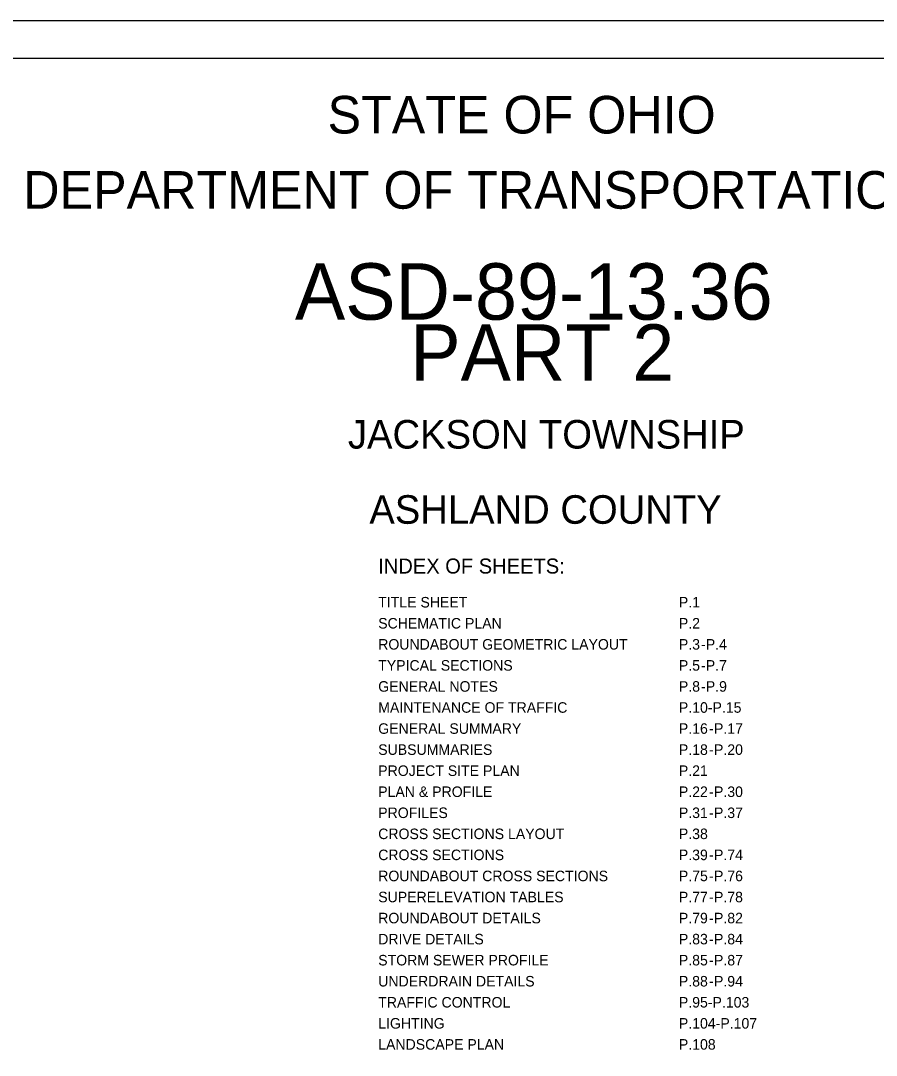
# Model space of a CAD drawing. Extents: x 0 to 72, y -85 to 22.
# Drawn here: x 9.89 to 21.27, y 8.24 to 22 of the extents above; entities that cross this region are included whole.
import ezdxf

# ---------------------------------------------------------------- set-up
doc = ezdxf.new("R2010")
doc.units = 0
for name, color, linetype in [('GM_X_Adjacent_County', 7, 'Continuous'), ('GM_X_County', 7, 'Continuous'), ('GM_X_Section', 7, 'Continuous')]:
    doc.layers.add(name, color=color, linetype=linetype)

msp = doc.modelspace()

# ---------------------------------------------------------------- linework, layer by layer
at = {"layer": 'GM_X_County'}
msp.add_lwpolyline([(1.5, 21.5), (33.5, 21.5), (33.5, 0.5), (1.5, 0.5)], close=True, dxfattribs=at)
at = {"layer": 'GM_X_Section'}
msp.add_lwpolyline([(0, 0), (34, 0), (34, 22), (0, 22)], close=True, dxfattribs=at)

# ---------------------------------------------------------------- texts
at = {"layer": 'GM_X_Adjacent_County'}
for s, height, p in [('STATE OF OHIO', 0.5, (13.968, 20.5)), ('DEPARTMENT OF TRANSPORTATION', 0.5, (9.92, 19.5)), ('ASD-89-13.36', 0.75, (13.534, 18.024)), ('PART 2', 0.75, (15.069, 17.212)), ('JACKSON TOWNSHIP', 0.38, (14.239, 16.31)), ('ASHLAND COUNTY', 0.38, (14.524, 15.31)), ('INDEX OF SHEETS:', 0.2, (14.642, 14.648)), ('TITLE SHEET', 0.14, (14.642, 14.197)), ('P.1', 0.14, (18.642, 14.197)), ('SCHEMATIC PLAN', 0.14, (14.642, 13.917)), ('P.2', 0.14, (18.642, 13.917)), ('ROUNDABOUT GEOMETRIC LAYOUT', 0.14, (14.642, 13.637)), ('P.3', 0.14, (18.642, 13.637)), ('P.4', 0.14, (19, 13.637)), ('-', 0.14, (18.935, 13.637)), ('TYPICAL SECTIONS', 0.14, (14.642, 13.357)), ('P.5', 0.14, (18.642, 13.357)), ('P.7', 0.14, (19, 13.357)), ('-', 0.14, (18.935, 13.357)), ('GENERAL NOTES', 0.14, (14.642, 13.077)), ('P.8', 0.14, (18.642, 13.077)), ('P.9', 0.14, (19, 13.077)), ('-', 0.14, (18.935, 13.077)), ('MAINTENANCE OF TRAFFIC', 0.14, (14.642, 12.797)), ('P.10-P.15', 0.14, (18.642, 12.797)), ('GENERAL SUMMARY', 0.14, (14.642, 12.517)), ('P.16', 0.14, (18.642, 12.517)), ('-', 0.14, (19.044, 12.517)), ('P.17', 0.14, (19.109, 12.517)), ('SUBSUMMARIES', 0.14, (14.642, 12.237)), ('P.18', 0.14, (18.642, 12.237)), ('-', 0.14, (19.044, 12.237)), ('P.20', 0.14, (19.109, 12.237)), ('PROJECT SITE PLAN', 0.14, (14.642, 11.957)), ('P.21', 0.14, (18.642, 11.957)), ('PLAN & PROFILE', 0.14, (14.642, 11.677)), ('P.22', 0.14, (18.642, 11.677)), ('-', 0.14, (19.044, 11.677)), ('P.30', 0.14, (19.109, 11.677)), ('PROFILES', 0.14, (14.642, 11.397)), ('P.31', 0.14, (18.642, 11.397)), ('-', 0.14, (19.044, 11.397)), ('P.37', 0.14, (19.109, 11.397)), ('CROSS SECTIONS LAYOUT', 0.14, (14.642, 11.117)), ('P.38', 0.14, (18.642, 11.117)), ('CROSS SECTIONS', 0.14, (14.642, 10.837)), ('P.39', 0.14, (18.642, 10.837)), ('-', 0.14, (19.044, 10.837)), ('P.74', 0.14, (19.109, 10.837)), ('ROUNDABOUT CROSS SECTIONS', 0.14, (14.642, 10.557)), ('P.75', 0.14, (18.642, 10.557)), ('-', 0.14, (19.044, 10.557)), ('P.76', 0.14, (19.109, 10.557)), ('SUPERELEVATION TABLES', 0.14, (14.642, 10.277)), ('P.77', 0.14, (18.642, 10.277)), ('-', 0.14, (19.044, 10.277)), ('P.78', 0.14, (19.109, 10.277)), ('ROUNDABOUT DETAILS', 0.14, (14.642, 9.997)), ('P.79', 0.14, (18.642, 9.997)), ('-', 0.14, (19.044, 9.997)), ('P.82', 0.14, (19.109, 9.997)), ('DRIVE DETAILS', 0.14, (14.642, 9.717)), ('P.83', 0.14, (18.642, 9.717)), ('-', 0.14, (19.044, 9.717)), ('P.84', 0.14, (19.109, 9.717)), ('STORM SEWER PROFILE', 0.14, (14.642, 9.437)), ('P.85', 0.14, (18.642, 9.437)), ('-', 0.14, (19.044, 9.437)), ('P.87', 0.14, (19.109, 9.437)), ('UNDERDRAIN DETAILS', 0.14, (14.642, 9.157)), ('P.88', 0.14, (18.642, 9.157)), ('-', 0.14, (19.044, 9.157)), ('P.94', 0.14, (19.109, 9.157)), ('TRAFFIC CONTROL', 0.14, (14.642, 8.877)), ('P.95-P.103', 0.14, (18.642, 8.877)), ('LIGHTING', 0.14, (14.642, 8.597)), ('P.104-P.107', 0.14, (18.642, 8.597)), ('LANDSCAPE PLAN', 0.14, (14.642, 8.317)), ('P.108', 0.14, (18.642, 8.317))]:
    msp.add_text(s, height=height, dxfattribs=at).set_placement(p)

doc.saveas('drawing.dxf')
